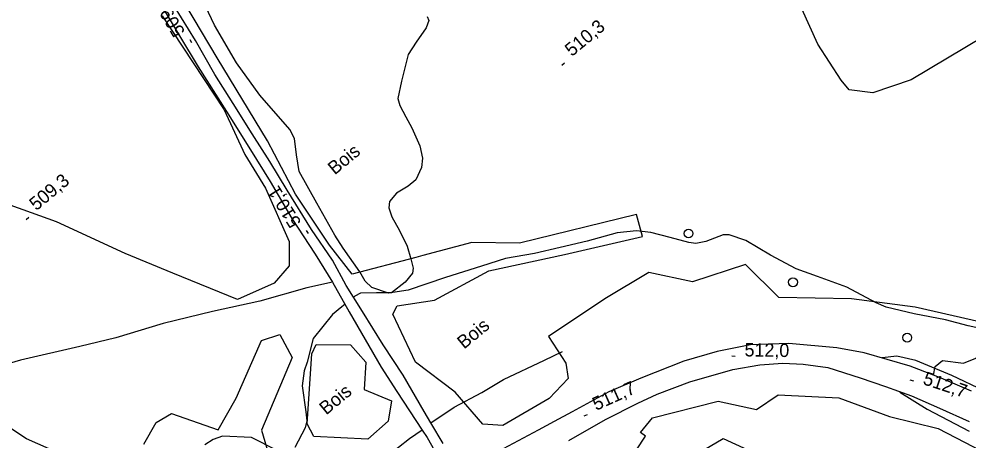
# Model space of a CAD drawing. Extents: x 347059 to 352153, y 6073752 to 6078601.
# Drawn here: x 348816 to 349136.4, y 6075988.4 to 6076130.4 of the extents above; entities that cross this region are included whole.
import ezdxf

# ---------------------------------------------------------------- set-up
doc = ezdxf.new("R2010")
doc.units = 0
for name, color, linetype in [('Level 1', 7, 'Continuous'), ('Level 2', 7, 'Continuous'), ('Level 21', 7, 'Continuous'), ('Level 22', 7, 'Continuous'), ('Level 3', 7, 'Continuous'), ('Level 36', 7, 'Continuous'), ('Level 37', 7, 'Continuous'), ('Level 4', 7, 'Continuous'), ('Level 44', 7, 'Continuous'), ('Level 7', 7, 'Continuous')]:
    doc.layers.add(name, color=color, linetype=linetype)

msp = doc.modelspace()

# ---------------------------------------------------------------- linework, layer by layer
at = {"layer": 'Level 1'}
for points in [[(348953.7, 6076131.32), (348954.26, 6076129.89), (348953.34, 6076127.47), (348949.97, 6076122.67), (348947.3, 6076118.48), (348946.48, 6076115.33), (348945.01, 6076109.44), (348943.76, 6076103.61), (348944.47, 6076101.22), (348946.46, 6076097.48), (348948.46, 6076093.75), (348951.16, 6076087.63), (348952.1, 6076083.54), (348951.72, 6076080.35), (348949.86, 6076076.17), (348947.28, 6076074.1), (348943.35, 6076071.68), (348941.01, 6076068.86), (348940.78, 6076066.76), (348941.73, 6076063.76), (348944.29, 6076059.15), (348946.95, 6076053.79), (348948.11, 6076049.51), (348948.93, 6076046.36), (348948.73, 6076044.7), (348946.24, 6076041.65), (348941.61, 6076038.1), (348936.57, 6076038.1), (348931.23, 6076038.01), (348929.29, 6076036.92), (348928.89, 6076036.59)], [(348925.99, 6076034.23), (348924.86, 6076033.31), (348921.71, 6076030.77), (348915.18, 6076022.64)], [(348915.18, 6076022.64), (348913.22, 6076014.71), (348912.21, 6076011.77), (348911.5, 6076006.76), (348912.81, 6075997.96), (348913.07, 6075994.95), (348912.52, 6075992.54), (348909, 6075985.94)], [(348902.85, 6075985.02), (348894.4, 6075989.31), (348884.68, 6075989.71), (348881.55, 6075988.6), (348878.73, 6075986.85)]]:
    msp.add_lwpolyline(points, dxfattribs=at)
at = {"layer": 'Level 2'}
for points in [[(349141.52, 6076004.99), (349130.57, 6076010.2), (349118.49, 6076015.23), (349112.03, 6076016.76), (349107.05, 6076016.12)], [(349113, 6076004.73), (349113.08, 6076004.59), (349122.22, 6075998.85), (349136.41, 6075991.38)]]:
    msp.add_lwpolyline(points, dxfattribs=at)
at = {"layer": 'Level 21'}
for points in [[(348861.79, 6076138.79), (348870.19, 6076124.73), (348876.47, 6076114.3), (348886.05, 6076099.27), (348894.1, 6076086.35), (348900.73, 6076075.6), (348908.09, 6076063.14), (348915.87, 6076051.17), (348921.79, 6076041.63), (348927.42, 6076031.7), (348932.78, 6076022.29)], [(348959.04, 6075987.31), (348954.93, 6075994.2), (348952.63, 6075998.08), (348945.61, 6076010.3), (348938.86, 6076020.58), (348931.9, 6076031.73), (348926.41, 6076040.58), (348921.71, 6076049.12), (348914.68, 6076059.46), (348906.45, 6076072.7), (348900.58, 6076082.36), (348894.65, 6076091.73), (348888.27, 6076101.93), (348882.09, 6076111.7), (348875.58, 6076123.22), (348868.5, 6076134.7)], [(348932.78, 6076022.29), (348938.14, 6076012.96), (348943.4, 6076004.83), (348951.98, 6075991.75), (348953.63, 6075989.25), (348958.59, 6075980.49)], [(349137.19, 6076004.9), (349127.02, 6076009.26), (349124.39, 6076010.3), (349116.54, 6076013.37), (349100.98, 6076017.89), (349091.75, 6076019.5), (349075.58, 6076020.97), (349062.64, 6076020.55), (349051.41, 6076018.25), (349040.17, 6076014.98), (349025.76, 6076009.29), (349014.97, 6076004.66), (349002.51, 6075997.9), (348996.49, 6075994.67), (348991.06, 6075991.8), (348979.3, 6075985.47)], [(349001.46, 6075988.24), (349013.84, 6075995.38), (349024.67, 6076000.86), (349031.22, 6076003.91), (349042.22, 6076008.11), (349056.78, 6076012.27), (349065.86, 6076013.82), (349073.57, 6076014.39), (349080.47, 6076014.05), (349088.72, 6076012.89), (349099.71, 6076009.44), (349108.17, 6076006.5), (349116.93, 6076003.29), (349126.47, 6075999.15), (349136.46, 6075994.64)]]:
    msp.add_lwpolyline(points, dxfattribs=at)
at = {"layer": 'Level 22'}
for points in [[(349124.39, 6076010.3), (349124.98, 6076013.19), (349127.47, 6076015.25), (349134.52, 6076014.37), (349138.69, 6076016.04), (349142.69, 6076019.36), (349147.83, 6076023.6), (349155.52, 6076026.09), (349159.88, 6076029.71), (349164.45, 6076031.26), (349175.07, 6076035.29), (349189.1, 6076039.75), (349210.76, 6076048.6), (349234.54, 6076057.42), (349241.48, 6076059.74), (349243.14, 6076059.92), (349245.05, 6076059.59)], [(348921.79, 6076041.63), (348913.05, 6076039.75), (348897.23, 6076035.29), (348881.25, 6076031.74), (348864.66, 6076027.68), (348848.65, 6076022.91), (348836.51, 6076020), (348816.51, 6076015.35), (348802.37, 6076011.23), (348794.58, 6076008.94), (348775.89, 6075999.83), (348768.71, 6075997.46), (348757.62, 6075996.17), (348751.75, 6075996.38), (348731.29, 6075999.88), (348712.39, 6076002.58), (348694.12, 6076003.83), (348685.76, 6076003.51)], [(348954.93, 6075994.2), (348962.8, 6075999.55), (348972.1, 6076004.43), (348979.39, 6076008.85), (348993.19, 6076015.37), (348999.29, 6076018.34)], [(348951.98, 6075991.75), (348947.68, 6075988.83), (348943.97, 6075985.89), (348933.28, 6075978.35), (348921.5, 6075970.65), (348909.87, 6075961.88), (348899.3, 6075959.24), (348888.89, 6075960.03), (348876.33, 6075965.02), (348861.15, 6075971.73), (348844.75, 6075978.63), (348830.08, 6075983.81), (348818.52, 6075988.88), (348806.4, 6075996.78)]]:
    msp.add_lwpolyline(points, dxfattribs=at)
at = {"layer": 'Level 3'}
for p, q in [((348874.34, 6076122.36), (348873.73, 6076123.39)), ((348999.06, 6076114.86), (348999.98, 6076115.63)), ((348818.48, 6076062.86), (348819.4, 6076063.63)), ((348913.61, 6076058.1), (348912.98, 6076059.12)), ((349056.34, 6076016.78), (349057.54, 6076016.76)), ((349116.46, 6076008.76), (349117.6, 6076008.38)), ((349006.65, 6075996.55), (349007.75, 6075997.04))]:
    msp.add_line(p, q, dxfattribs=at)
at = {"layer": 'Level 36'}
for centre in [(349041.8, 6076058.09), (349077.01, 6076041.64), (349115.53, 6076022.97)]:
    msp.add_circle(centre, 1.5, dxfattribs=at)
at = {"layer": 'Level 37'}
msp.add_lwpolyline([(349160.73, 6075498.89), (349134.29, 6075542.79), (349102.45, 6075595.52), (349073.5, 6075643.88), (349047.55, 6075685.37), (349016.57, 6075735.98), (348983.34, 6075791.45), (348957.42, 6075833.08), (348930.88, 6075881.4), (348949.9, 6075924.16), (348980.68, 6075945.55), (349018.14, 6075968.15), (349053.46, 6075988.98), (349105.83, 6075964.84), (349145.26, 6075946.36)], dxfattribs=at)
at = {"layer": 'Level 4'}
msp.add_lwpolyline([(349144.85, 6076025.01), (349136.13, 6076026.99), (349128.44, 6076029), (349117.84, 6076030.98), (349108.46, 6076033.23), (349105.07, 6076034.68), (349095.19, 6076040.04), (349085.31, 6076043.59), (349078.09, 6076046.21), (349069.46, 6076050.8), (349061.09, 6076055.7), (349055.49, 6076057.64), (349053.45, 6076057.66), (349047.63, 6076055.44), (349044.24, 6076054.73), (349041.89, 6076055.02), (349035.58, 6076056.74), (349029.13, 6076058.43), (349024.26, 6076058.95), (349017.69, 6076058.36), (349007.67, 6076055.5), (348998.46, 6076053.39), (348989.91, 6076051.3), (348980.08, 6076049.65), (348972.01, 6076047.06), (348959.9, 6076043.21), (348947.21, 6076038.95), (348940.68, 6076037.95), (348935.05, 6076039.93), (348932.78, 6076042.02), (348930.99, 6076045.17), (348925.33, 6076053.14), (348922.58, 6076057.53), (348916.49, 6076068.28), (348910.52, 6076079.05), (348909.6, 6076084.58), (348908.97, 6076090.13), (348907.33, 6076093.18), (348897.3, 6076104.78), (348889.42, 6076115.69), (348882, 6076128.39), (348877.04, 6076138.95)], dxfattribs=at)
at = {"layer": 'Level 44'}
for points in [[(349000.43, 6076014.38), (349001.18, 6076009.16), (348994.84, 6076002.46), (348979.17, 6075993.32), (348972.49, 6075993.76), (348963.08, 6076004.52), (348949.78, 6076014.73), (348942.09, 6076030.83), (348943.5, 6076033.65), (348956.13, 6076035.61), (348974.51, 6076045.49), (349000, 6076050.96), (349026.29, 6076057.09), (349024.28, 6076064.55), (348984.8, 6076054.79), (348968.69, 6076055.02), (348952.15, 6076050.71), (348949.85, 6076050.02), (348928.43, 6076044.35), (348920.73, 6076054.14), (348909.23, 6076071.39), (348899.84, 6076089.35), (348882.86, 6076117.33), (348859.2, 6076157.11)], [(348864.33, 6076131.53), (348885.2, 6076099.79), (348892.15, 6076084.76), (348899.12, 6076073.33), (348907.12, 6076055.42), (348907.18, 6076047.23), (348902.13, 6076041.38), (348889.66, 6076035.81), (348867.88, 6076044.66), (348851.81, 6076051.35), (348828.65, 6076062.05), (348804.5, 6076070.67), (348796.01, 6076083.6), (348783.22, 6076093.49), (348773.26, 6076096.61), (348756.77, 6076102.17), (348743.78, 6076113.7), (348729.49, 6076125.19), (348722.21, 6076134.2)], [(349150.29, 6076025.92), (349118.22, 6076033.24), (349096.7, 6076036.01), (349072.26, 6076036.5), (349061, 6076047.67), (349043.09, 6076041.77), (349028.4, 6076044.98), (349013.58, 6076036.1), (348994.62, 6076023.34), (349000.43, 6076014.38)], [(348858.17, 6075987.06), (348862.29, 6075994.38), (348867.48, 6075997.35), (348883.18, 6075991.82), (348889.25, 6076002.57), (348897.85, 6076022.01), (348903.94, 6076024.07), (348908.2, 6076016.24), (348897.83, 6075991.72), (348901.19, 6075980.28)], [(348932.99, 6076014.71), (348932.46, 6076005.43), (348941.61, 6076001.65), (348940.57, 6075994.78), (348933.61, 6075988.7), (348915.44, 6075989.62), (348913.22, 6075993.92), (348914.75, 6076017.52), (348916.19, 6076020.66), (348927.81, 6076020.59), (348932.99, 6076014.71)], [(349064.7, 6075998.76), (349072.04, 6076003.66), (349092.51, 6076002.7), (349109.54, 6075996.32), (349125.97, 6075992.29), (349143.72, 6075983.07)], [(349024.27, 6075985.08), (349027.32, 6075989.71), (349025.64, 6075991.01), (349029.7, 6075995.88), (349051.76, 6076001.49), (349064.7, 6075998.76)]]:
    msp.add_lwpolyline(points, dxfattribs=at)
at = {"layer": 'Level 7'}
msp.add_lwpolyline([(349141.4, 6076124.53), (349116.85, 6076109.96), (349103.89, 6076105.49), (349095.95, 6076106.53), (349093.23, 6076109.81), (349085.41, 6076121.89), (349077.31, 6076139.88)], dxfattribs=at)

# ---------------------------------------------------------------- texts
at = {"layer": 'Level 3'}
for s, rotation, p in [('509,7', 120.6487, (348872.18, 6076126.1)), ('510,3', 39.62, (349002.42, 6076117.58)), ('509,3', 39.62, (348821.84, 6076065.58)), ('510,1', 121.7755, (348911.38, 6076061.81)), ('512,0', 359.0657, (349060.66, 6076016.65)), ('512,7', 341.4956, (349120.54, 6076007.34)), ('511,7', 23.9828, (349010.62, 6075998.26))]:
    msp.add_text(s, height=4.5, rotation=rotation, dxfattribs=at).set_placement(p)
at = {"layer": 'Level 44'}
for p in [(348922.5, 6076077.67), (348966.1, 6076018.93), (348919.62, 6075996.7)]:
    msp.add_text('Bois', height=4.5, rotation=39.568, dxfattribs=at).set_placement(p)

doc.saveas('drawing.dxf')
